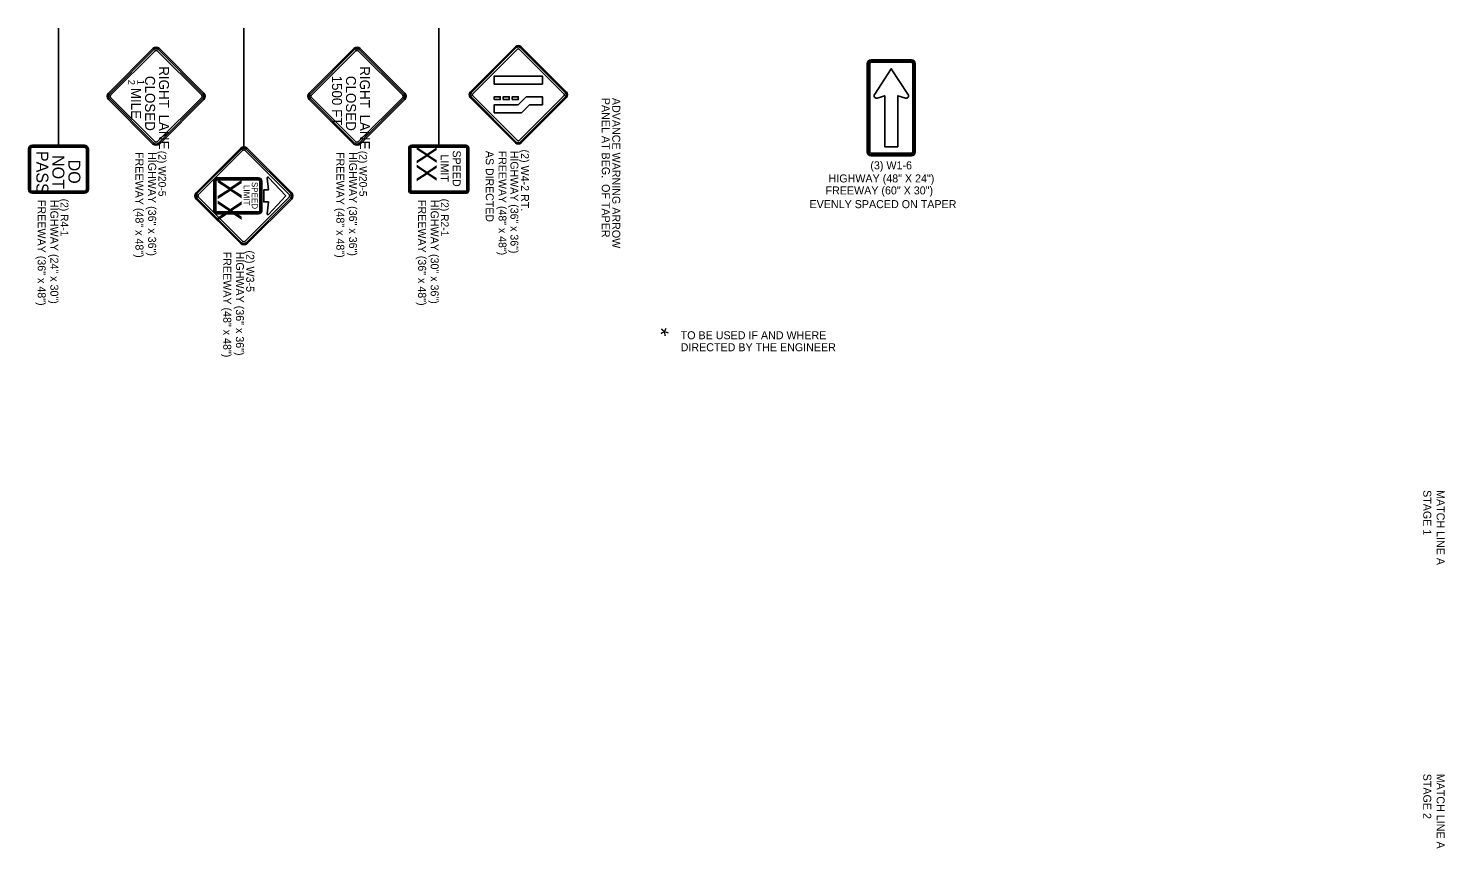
# Model space of a CAD drawing. Extents: x 1930579 to 1937521, y 596183 to 597599.
# Drawn here: x 1934052 to 1935114, y 596519 to 597134 of the extents above; entities that cross this region are included whole.
import ezdxf

# ---------------------------------------------------------------- set-up
doc = ezdxf.new("R2010")
doc.units = 0
for name, color, linetype in [('Default', 7, 'Continuous'), ('P_TC_Signs_Permanent', 7, 'Continuous'), ('P_TC_Signs_Temporary', 7, 'Continuous'), ('R_Annotation', 7, 'Continuous')]:
    doc.layers.add(name, color=color, linetype=linetype)

msp = doc.modelspace()

# ---------------------------------------------------------------- linework, layer by layer
at = {"layer": 'P_TC_Signs_Permanent'}
for p, q in [((1934383.1, 597086.1), (1934417.1, 597120.1)), ((1934713.9, 597110.3), (1934683.6, 597110.3)), ((1934713.9, 597109.5), (1934683.6, 597109.5)), ((1934713.9, 597108.4), (1934683.6, 597108.4)), ((1934437.2, 597092), (1934437.2, 597098)), ((1934680.8, 597107.5), (1934680.8, 597041.1)), ((1934681.5, 597107.5), (1934681.5, 597041.1)), ((1934682.6, 597107.5), (1934682.6, 597041.1)), ((1934714.9, 597041.1), (1934714.9, 597107.5)), ((1934716, 597041.1), (1934716, 597107.5)), ((1934716.8, 597041.1), (1934716.8, 597107.5)), ((1934417.1, 597047.9), (1934383.1, 597081.9)), ((1934455.3, 597081.9), (1934421.3, 597047.9)), ((1934093.9, 597046.2), (1934054.9, 597046.2)), ((1934093.9, 597045.6), (1934054.9, 597045.6)), ((1934093.9, 597044.7), (1934054.9, 597044.7)), ((1934211.1, 597044), (1934177.7, 597010.6)), ((1934249.3, 597010.6), (1934215.9, 597044)), ((1934337, 597043.9), (1934337, 597012.4)), ((1934337.6, 597043.9), (1934337.6, 597012.4)), ((1934338.5, 597043.9), (1934338.5, 597012.4)), ((1934379.8, 597046.2), (1934339.3, 597046.2)), ((1934379.8, 597045.6), (1934339.3, 597045.6)), ((1934379.8, 597044.7), (1934339.3, 597044.7)), ((1934380.5, 597012.4), (1934380.5, 597043.9)), ((1934381.5, 597012.4), (1934381.5, 597043.9)), ((1934382, 597012.4), (1934382, 597043.9)), ((1934051.9, 597043.2), (1934051.9, 597013.2)), ((1934052.5, 597043.2), (1934052.5, 597013.2)), ((1934053.4, 597043.2), (1934053.4, 597013.2)), ((1934095.4, 597013.2), (1934095.4, 597043.2)), ((1934096.3, 597013.2), (1934096.3, 597043.2)), ((1934096.9, 597013.2), (1934096.9, 597043.2)), ((1934211.7, 597043.3), (1934178.3, 597009.9)), ((1934212.7, 597042.4), (1934179.3, 597009)), ((1934247.7, 597009), (1934214.3, 597042.4)), ((1934248.6, 597009.9), (1934215.2, 597043.3)), ((1934683.6, 597040.2), (1934713.9, 597040.2)), ((1934683.6, 597039), (1934713.9, 597039)), ((1934683.6, 597038.3), (1934713.9, 597038.3)), ((1934190.9, 596997.1), (1934190.9, 597019.3)), ((1934193.3, 597021.7), (1934224.5, 597021.7)), ((1934226.9, 597019.3), (1934226.9, 596997.1)), ((1934054.9, 597011.7), (1934093.9, 597011.7)), ((1934054.9, 597010.8), (1934093.9, 597010.8)), ((1934054.9, 597010.2), (1934093.9, 597010.2)), ((1934177.7, 597005.8), (1934211.1, 596972.4)), ((1934178.3, 597006.4), (1934211.7, 596973)), ((1934179.3, 597007.4), (1934212.7, 596974)), ((1934214.3, 596974), (1934247.7, 597007.4)), ((1934215.2, 596973), (1934248.6, 597006.4)), ((1934215.9, 596972.4), (1934249.3, 597005.8)), ((1934339.3, 597011.7), (1934379.8, 597011.7)), ((1934339.3, 597010.8), (1934379.8, 597010.8)), ((1934339.3, 597010.2), (1934379.8, 597010.2)), ((1934224.5, 596994.7), (1934193.3, 596994.7))]:
    msp.add_line(p, q, dxfattribs=at)
for points in [[(1934417.7, 597119.4), (1934383.8, 597085.5)], [(1934384.8, 597084.4), (1934418.8, 597118.4)], [(1934419.6, 597118.4), (1934453.6, 597084.4)], [(1934454.6, 597085.5), (1934420.7, 597119.4)], [(1934421.3, 597120.1), (1934438.3, 597103.1), (1934455.3, 597086.1)], [(1934711.2, 597084.5), (1934698.8, 597103.5), (1934686.4, 597084.5)], [(1934383.8, 597082.5), (1934417.7, 597048.6)], [(1934418.8, 597049.6), (1934384.8, 597083.6)], [(1934453.6, 597083.6), (1934419.6, 597049.6)], [(1934420.7, 597048.6), (1934454.6, 597082.5)], [(1934688.1, 597081.6), (1934693.9, 597083.3), (1934693.9, 597045), (1934703.6, 597045), (1934703.6, 597083.3), (1934709.4, 597081.6)], [(1934191.5, 597019.3), (1934191.5, 596997.1)], [(1934192.4, 596997.1), (1934192.4, 597019.3)], [(1934224.5, 597021.1), (1934193.3, 597021.1)], [(1934193.3, 597020.2), (1934224.5, 597020.2)], [(1934225.4, 597019.3), (1934225.4, 597008.2), (1934225.4, 596997.1)], [(1934226.3, 596997.1), (1934226.3, 597008.2), (1934226.3, 597019.3)], [(1934230.8, 597021.6), (1934231.9, 597012.7), (1934228.4, 597012.7), (1934228.4, 597003.7), (1934231.9, 597003.7), (1934230.8, 596994.8)], [(1934231.8, 596994.3), (1934244.9, 597008.2), (1934231.8, 597022.1)], [(1934224.5, 596996.2), (1934193.3, 596996.2)], [(1934193.3, 596995.3), (1934224.5, 596995.3)]]:
    msp.add_lwpolyline(points, dxfattribs=at)
for points in [[(1934401.2, 597092), (1934401.2, 597098), (1934437.2, 597098), (1934437.2, 597092)], [(1934401.2, 597080.4), (1934401.2, 597082.5), (1934405.7, 597082.5), (1934405.7, 597080.4)], [(1934401.2, 597070.5), (1934401.2, 597076.5), (1934419.2, 597076.5), (1934425.2, 597082.5), (1934437.2, 597082.5), (1934437.2, 597076.5), (1934427.7, 597076.5), (1934421.7, 597070.5)], [(1934407.9, 597080.4), (1934407.9, 597082.5), (1934412.4, 597082.5), (1934412.4, 597080.4)], [(1934414.7, 597080.4), (1934414.7, 597082.5), (1934419.2, 597082.5), (1934419.2, 597080.4)]]:
    msp.add_lwpolyline(points, close=True, dxfattribs=at)
for centre, radius, start, end in [((1934419.2, 597117.9), 3, 45, 135), ((1934419.2, 597117.9), 2.1, 45, 135), ((1934419.2, 597117.9), 0.6, 45, 135), ((1934683.6, 597107.5), 2.81, 90, 180), ((1934683.6, 597107.5), 2.06, 90, 180), ((1934683.6, 597107.5), 0.938, 90, 180), ((1934713.9, 597107.5), 2.81, 360, 90), ((1934713.9, 597107.5), 2.06, 360, 90), ((1934713.9, 597107.5), 0.938, 360, 90), ((1934385.3, 597084), 3, 135, 225), ((1934385.3, 597084), 2.1, 135, 225), ((1934385.3, 597084), 0.6, 135, 225), ((1934453.1, 597084), 0.6, 315, 45), ((1934453.1, 597084), 2.1, 315, 45), ((1934453.1, 597084), 3, 315, 45), ((1934687.6, 597083.3), 1.76, 146.5994, 285.9691), ((1934623.6, 597125.5), 75, 326.5994, 326.857), ((1934709.9, 597083.3), 1.8, 254.0309, 33.4755), ((1934773.9, 597125.6), 75, 213.2286, 213.4755), ((1934054.9, 597043.2), 3, 90, 180), ((1934054.9, 597043.2), 2.4, 90, 180), ((1934054.9, 597043.2), 1.5, 90, 180), ((1934093.9, 597043.2), 3, 360, 90), ((1934093.9, 597043.2), 2.4, 360, 90), ((1934093.9, 597043.2), 1.5, 360, 90), ((1934213.5, 597041.6), 3.38, 45, 135), ((1934213.5, 597041.6), 2.44, 45, 135), ((1934339.3, 597043.9), 2.25, 90, 180), ((1934339.3, 597043.9), 1.69, 90, 180), ((1934339.3, 597043.9), 0.75, 90, 180), ((1934379.8, 597043.9), 2.25, 360, 90), ((1934379.8, 597043.9), 1.69, 360, 90), ((1934379.8, 597043.9), 0.75, 360, 90), ((1934419.2, 597050), 3, 225, 315), ((1934419.2, 597050), 2.1, 225, 315), ((1934419.2, 597050), 0.6, 225, 315), ((1934213.5, 597041.6), 1.13, 45, 135), ((1934683.6, 597041.1), 2.81, 180, 270), ((1934683.6, 597041.1), 2.06, 180, 270), ((1934683.6, 597041.1), 0.937, 180, 270), ((1934713.9, 597041.1), 2.81, 270, 360), ((1934713.9, 597041.1), 2.06, 270, 360), ((1934713.9, 597041.1), 0.938, 270, 360), ((1934054.9, 597013.2), 3, 180, 270), ((1934054.9, 597013.2), 2.4, 180, 270), ((1934054.9, 597013.2), 1.5, 180, 270), ((1934093.9, 597013.2), 3, 270, 360), ((1934093.9, 597013.2), 2.4, 270, 360), ((1934093.9, 597013.2), 1.5, 270, 360), ((1934193.3, 597019.3), 2.4, 90, 180), ((1934193.3, 597019.3), 1.8, 90, 180), ((1934193.3, 597019.3), 0.9, 90, 180), ((1934224.5, 597019.3), 2.4, 0, 90), ((1934224.5, 597019.3), 1.8, 0, 90), ((1934224.5, 597019.3), 0.9, 0, 90), ((1934231.4, 597021.7), 0.563, 43.3117, 187.125), ((1934339.3, 597012.4), 2.25, 180, 270), ((1934339.3, 597012.4), 1.69, 180, 270), ((1934339.3, 597012.4), 0.75, 180, 270), ((1934379.8, 597012.4), 2.25, 270, 360), ((1934379.8, 597012.4), 1.69, 270, 360), ((1934379.8, 597012.4), 0.75, 270, 360), ((1934180.1, 597008.2), 3.38, 135, 225), ((1934180.1, 597008.2), 2.44, 135, 225), ((1934180.1, 597008.2), 1.13, 135, 225), ((1934246.9, 597008.2), 1.13, 315, 45), ((1934246.9, 597008.2), 2.44, 315, 45), ((1934246.9, 597008.2), 3.38, 315, 45), ((1934193.3, 596997.1), 2.4, 180, 270), ((1934193.3, 596997.1), 1.8, 180, 270), ((1934193.3, 596997.1), 0.9, 180, 270), ((1934224.5, 596997.1), 2.4, 270, 0), ((1934224.5, 596997.1), 1.8, 270, 0), ((1934224.5, 596997.1), 0.9, 270, 0), ((1934231.4, 596994.7), 0.563, 172.875, 316.6883), ((1934213.5, 596974.8), 3.38, 225, 315), ((1934213.5, 596974.8), 2.44, 225, 315), ((1934213.5, 596974.8), 1.13, 225, 315)]:
    msp.add_arc(centre, radius, start, end, dxfattribs=at)
at = {"layer": 'P_TC_Signs_Temporary'}
for p, q in [((1934111.9, 597085.3), (1934145.3, 597118.7)), ((1934150.1, 597118.7), (1934183.5, 597085.3)), ((1934262.5, 597085.3), (1934295.9, 597118.7)), ((1934300.6, 597118.7), (1934334.1, 597085.3)), ((1934112.6, 597084.6), (1934146, 597118)), ((1934113.5, 597083.7), (1934146.9, 597117.1)), ((1934148.5, 597117.1), (1934181.9, 597083.7)), ((1934149.4, 597118), (1934182.8, 597084.6)), ((1934263.1, 597084.6), (1934296.5, 597118)), ((1934264.1, 597083.7), (1934297.5, 597117.1)), ((1934299.1, 597117.1), (1934332.5, 597083.7)), ((1934300, 597118), (1934333.4, 597084.6)), ((1934145.3, 597047.1), (1934111.9, 597080.5)), ((1934146, 597047.8), (1934112.6, 597081.2)), ((1934146.9, 597048.7), (1934113.5, 597082.1)), ((1934181.9, 597082.1), (1934148.5, 597048.7)), ((1934182.8, 597081.2), (1934149.4, 597047.8)), ((1934183.5, 597080.5), (1934150.1, 597047.1)), ((1934295.9, 597047.1), (1934262.5, 597080.5)), ((1934296.5, 597047.8), (1934263.1, 597081.2)), ((1934297.5, 597048.7), (1934264.1, 597082.1)), ((1934332.5, 597082.1), (1934299.1, 597048.7)), ((1934333.4, 597081.2), (1934300, 597047.8)), ((1934334.1, 597080.5), (1934300.6, 597047.1))]:
    msp.add_line(p, q, dxfattribs=at)
for centre, radius, start, end in [((1934147.7, 597116.3), 3.37, 45, 135), ((1934147.7, 597116.3), 2.44, 45, 135), ((1934298.3, 597116.3), 3.37, 45, 135), ((1934298.3, 597116.3), 2.44, 45, 135), ((1934147.7, 597116.3), 1.12, 45, 135), ((1934298.3, 597116.3), 1.12, 45, 135), ((1934114.3, 597082.9), 3.37, 135, 225), ((1934114.3, 597082.9), 2.44, 135, 225), ((1934114.3, 597082.9), 1.13, 135, 225), ((1934181.1, 597082.9), 1.13, 315, 45), ((1934181.1, 597082.9), 2.44, 315, 45), ((1934181.1, 597082.9), 3.38, 315, 45), ((1934264.8, 597082.9), 3.37, 135, 225), ((1934264.8, 597082.9), 2.44, 135, 225), ((1934264.8, 597082.9), 1.13, 135, 225), ((1934331.7, 597082.9), 1.13, 315, 45), ((1934331.7, 597082.9), 2.44, 315, 45), ((1934331.7, 597082.9), 3.38, 315, 45), ((1934147.7, 597049.5), 3.38, 225, 315), ((1934147.7, 597049.5), 2.44, 225, 315), ((1934147.7, 597049.5), 1.12, 225, 315), ((1934298.3, 597049.5), 3.38, 225, 315), ((1934298.3, 597049.5), 2.44, 225, 315), ((1934298.3, 597049.5), 1.12, 225, 315)]:
    msp.add_arc(centre, radius, start, end, dxfattribs=at)
at = {"layer": 'R_Annotation'}
for p, q in [((1934074.4, 597133.9), (1934074.4, 597046.2)), ((1934213.5, 597133.9), (1934213.5, 597045)), ((1934359.5, 597133.9), (1934359.5, 597046.2))]:
    msp.add_line(p, q, dxfattribs=at)

# ---------------------------------------------------------------- texts
at = {"layer": 'Default'}
for s, p in [('STAGE 1', (1935097.6, 596787.6)), ('MATCH LINE A ', (1935107.6, 596787.6)), ('STAGE 2', (1935097.6, 596574.9)), ('MATCH LINE A ', (1935107.6, 596574.9))]:
    msp.add_text(s, height=6, rotation=270, dxfattribs=at).set_placement(p)
at = {"layer": 'P_TC_Signs_Permanent'}
for s, height, rotation, p in [('XX', 15, 270, (1934343, 597045.5)), ('PASS', 9, 270, (1934057.9, 597041.9)), ('NOT', 9, 269.9596, (1934069.9, 597038.8)), ('DO', 9, 270, (1934081.9, 597035.4)), ('LIMIT', 6, 270, (1934361, 597039.2)), ('SPEED', 6, 270, (1934370, 597042.3)), ('XX', 18, 270, (1934193.9, 597021.3)), ('LIMIT', 4.5, 270, (1934213.4, 597016.4)), ('SPEED', 4.5, 270, (1934219.4, 597018.7))]:
    msp.add_text(s, height=height, rotation=rotation, dxfattribs=at).set_placement(p)
at = {"layer": 'P_TC_Signs_Temporary'}
for s, height, p in [('CLOSED', 7.5, (1934139.4, 597098.2)), ('RIGHT\u2002LANE', 7.5, (1934149.8, 597105.4)), ('1500 FT', 7.5, (1934279.5, 597098.4)), ('CLOSED', 7.5, (1934290, 597098.2)), ('RIGHT\u2002LANE', 7.5, (1934300.4, 597105.4)), ('2', 5.25, (1934126.6, 597095.3)), (' MILE', 7.5, (1934128.9, 597092)), ('1', 5.25, (1934133.6, 597095.3))]:
    msp.add_text(s, height=height, rotation=270, dxfattribs=at).set_placement(p)
at = {"layer": 'R_Annotation'}
for s, height, rotation, p in [('PANEL AT BEG.  OF TAPER', 6, 270, (1934481.8, 597081.7)), ('ADVANCE WARNING ARROW', 6, 270, (1934489.6, 597081.7)), ('FREEWAY (48" x 48")', 6, 270, (1934132.2, 597041.1)), ('HIGHWAY (36" x 36")', 6, 270, (1934141.7, 597041.1)), ('(2) W20-5', 5.76, 270, (1934149.4, 597042)), ('FREEWAY (48" x 48")', 6, 270, (1934282.8, 597041.1)), ('HIGHWAY (36" x 36")', 6, 270, (1934292.3, 597041.1)), ('(2) W20-5', 5.76, 270, (1934300, 597042)), ('AS DIRECTED ', 5.925, 270, (1934394.8, 597041.9)), ('FREEWAY (48" x 48")', 5.925, 270, (1934404.4, 597042)), ('HIGHWAY (36" x 36")', 5.925, 270, (1934413.3, 597042)), ('(2) W4-2 RT.', 6, 270, (1934421.2, 597043)), ('(3) W1-6', 6, 0.0075, (1934683.1, 597028.1)), ('HIGHWAY (48" X 24")', 6, 0.0075, (1934651.8, 597018.3)), ('FREEWAY (60" X 30")', 6, 0.0075, (1934649.5, 597009.3)), ('FREEWAY (36" x 48")', 6, 270, (1934058.9, 597005.2)), ('HIGHWAY (24" x 30")', 6, 270, (1934068.4, 597005.2)), ('(2) R4-1', 5.76, 270, (1934076.1, 597006.1)), ('FREEWAY (36" x 48")', 6, 270, (1934344.1, 597005.2)), ('HIGHWAY (30" x 36")', 6, 270, (1934353.5, 597005.2)), ('(2) R2-1', 5.76, 270, (1934361.2, 597006.1)), ('EVENLY SPACED ON TAPER', 6, 0.0075, (1934637.5, 596999)), ('FREEWAY (48" x 48")', 6, 270, (1934198, 596966.4)), ('HIGHWAY (36" x 36")', 6, 270, (1934207.5, 596966.4)), ('(2) W3-5', 6, 270, (1934215.2, 596967.3)), ('*', 12, 45, (1934532.7, 596897.8)), ('TO BE USED IF AND WHERE', 6, 360, (1934540.9, 596900.7)), ('DIRECTED BY THE ENGINEER', 6, 360, (1934540.9, 596891.7))]:
    msp.add_text(s, height=height, rotation=rotation, dxfattribs=at).set_placement(p)

doc.saveas('drawing.dxf')
